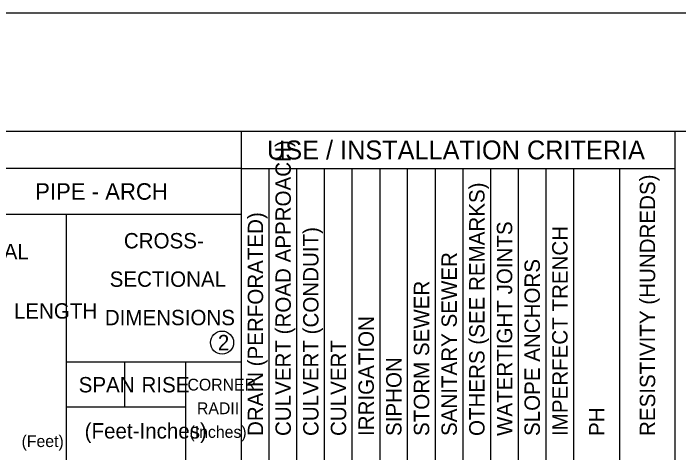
# Model space of a CAD drawing. Extents: x 0 to 1.42, y 0 to 0.92.
# Drawn here: x 0.2763 to 0.5109, y 0.7618 to 0.9167 of the extents above; entities that cross this region are included whole.
import ezdxf

# ---------------------------------------------------------------- set-up
doc = ezdxf.new("R2010")
doc.units = 0
for name, color, linetype in [('#plot_shape', 7, 'Continuous'), ('P_ODOT_PLAN_Border', 7, 'Continuous'), ('P_ODOT_PLAN_General', 7, 'Continuous'), ('P_RDWY_PLAN_NotesTx', 7, 'Continuous')]:
    doc.layers.add(name, color=color, linetype=linetype)

msp = doc.modelspace()

# ---------------------------------------------------------------- linework, layer by layer
at = {"layer": '#plot_shape'}
msp.add_lwpolyline([(0, 0), (1.41667, 0), (1.41667, 0.91667), (0, 0.91667)], close=True, dxfattribs=at)
at = {"layer": 'P_ODOT_PLAN_Border'}
msp.add_lwpolyline([(0.0625, 0.04167), (1.39583, 0.04167), (1.39583, 0.875), (0.0625, 0.875)], close=True, dxfattribs=at)
at = {"layer": 'P_ODOT_PLAN_General'}
for p, q in [((0.35681, 0.26037), (0.35681, 0.875)), ((0.50965, 0.26037), (0.50965, 0.875)), ((0.35681, 0.86199), (0.10478, 0.86199)), ((0.35681, 0.86199), (0.50965, 0.86199)), ((0.36656, 0.26037), (0.36656, 0.86199)), ((0.37632, 0.26037), (0.37632, 0.86199)), ((0.38608, 0.26037), (0.38608, 0.86199)), ((0.39583, 0.26037), (0.39583, 0.86199)), ((0.40559, 0.26037), (0.40559, 0.86199)), ((0.41534, 0.26037), (0.41534, 0.86199)), ((0.4251, 0.26037), (0.4251, 0.86199)), ((0.43486, 0.26037), (0.43486, 0.86199)), ((0.44461, 0.26037), (0.44461, 0.86199)), ((0.45437, 0.26037), (0.45437, 0.86199)), ((0.46412, 0.26037), (0.46412, 0.86199)), ((0.47388, 0.26037), (0.47388, 0.86199)), ((0.49014, 0.26037), (0.49014, 0.86199)), ((0.35681, 0.84573), (0.25112, 0.84573)), ((0.29502, 0.26037), (0.29502, 0.84573)), ((0.35681, 0.7937), (0.29502, 0.7937)), ((0.31564, 0.77779), (0.31564, 0.7937)), ((0.33711, 0.26037), (0.33711, 0.7937)), ((0.33711, 0.77779), (0.29502, 0.77779))]:
    msp.add_line(p, q, dxfattribs=at)
at = {"layer": 'P_RDWY_PLAN_NotesTx'}
msp.add_circle((0.34991, 0.8006), 0.00407, dxfattribs=at)

# ---------------------------------------------------------------- texts
for s, height, p in [('USE / INSTALLATION CRITERIA', 0.0066667, (0.36575, 0.86516)), ('PIPE - ARCH', 0.0058333, (0.284, 0.85095)), ('CROSS-', 0.005417, (0.31529, 0.8338)), ('HELICAL', 0.005417, (0.25158, 0.82997)), ('SECTIONAL', 0.005417, (0.31028, 0.82026)), ('LENGTH', 0.005417, (0.27652, 0.80905)), ('DIMENSIONS', 0.005417, (0.30858, 0.80672)), ('2', 0.00542, (0.34842, 0.79789)), ('SPAN', 0.005417, (0.29935, 0.78304)), ('RISE', 0.005417, (0.32151, 0.78304)), ('CORNER', 0.004167, (0.33772, 0.78369)), ('RADII', 0.004167, (0.34106, 0.77536)), ('(Feet-Inches)', 0.0054167, (0.30147, 0.76678)), ('(Inches)', 0.004167, (0.33843, 0.76702)), ('(Feet)', 0.004167, (0.27923, 0.76378))]:
    msp.add_text(s, height=height, dxfattribs=at).set_placement(p)
for s, height, p in [('CULVERT (ROAD APPROACH)', 0.0054167, (0.37415, 0.76768)), ('RESISTIVITY (HUNDREDS)', 0.0054167, (0.5026, 0.76768)), ('OTHERS (SEE REMARKS)', 0.0054167, (0.44244, 0.76768)), ('DRAIN (PERFORATED)', 0.0054167, (0.36439, 0.76768)), ('WATERTIGHT JOINTS', 0.0054167, (0.4522, 0.76768)), ('CULVERT (CONDUIT)', 0.0054167, (0.3839, 0.76768)), ('IMPERFECT TRENCH', 0.0054167, (0.47171, 0.76768)), ('SANITARY SEWER', 0.0054167, (0.43268, 0.76768)), ('SLOPE ANCHORS', 0.0054167, (0.46195, 0.76768)), ('STORM SEWER', 0.0054167, (0.42293, 0.76768)), ('IRRIGATION', 0.005417, (0.40342, 0.76768)), ('CULVERT', 0.005417, (0.39366, 0.76768)), ('SIPHON', 0.005417, (0.41317, 0.76768)), ('PH', 0.005417, (0.48472, 0.76768))]:
    msp.add_text(s, height=height, rotation=90, dxfattribs=at).set_placement(p)

doc.saveas('drawing.dxf')
